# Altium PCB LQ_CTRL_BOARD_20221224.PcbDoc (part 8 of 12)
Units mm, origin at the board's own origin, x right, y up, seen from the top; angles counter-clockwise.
Board outline 260 x 142 mm, 6 copper layers (Top Layer, Mid-Layer 1, Mid-Layer 2, Mid-Layer 3, Mid-Layer 4, Bottom Layer); 1105 components, 1039 nets, 3898 pads, 1277 vias.
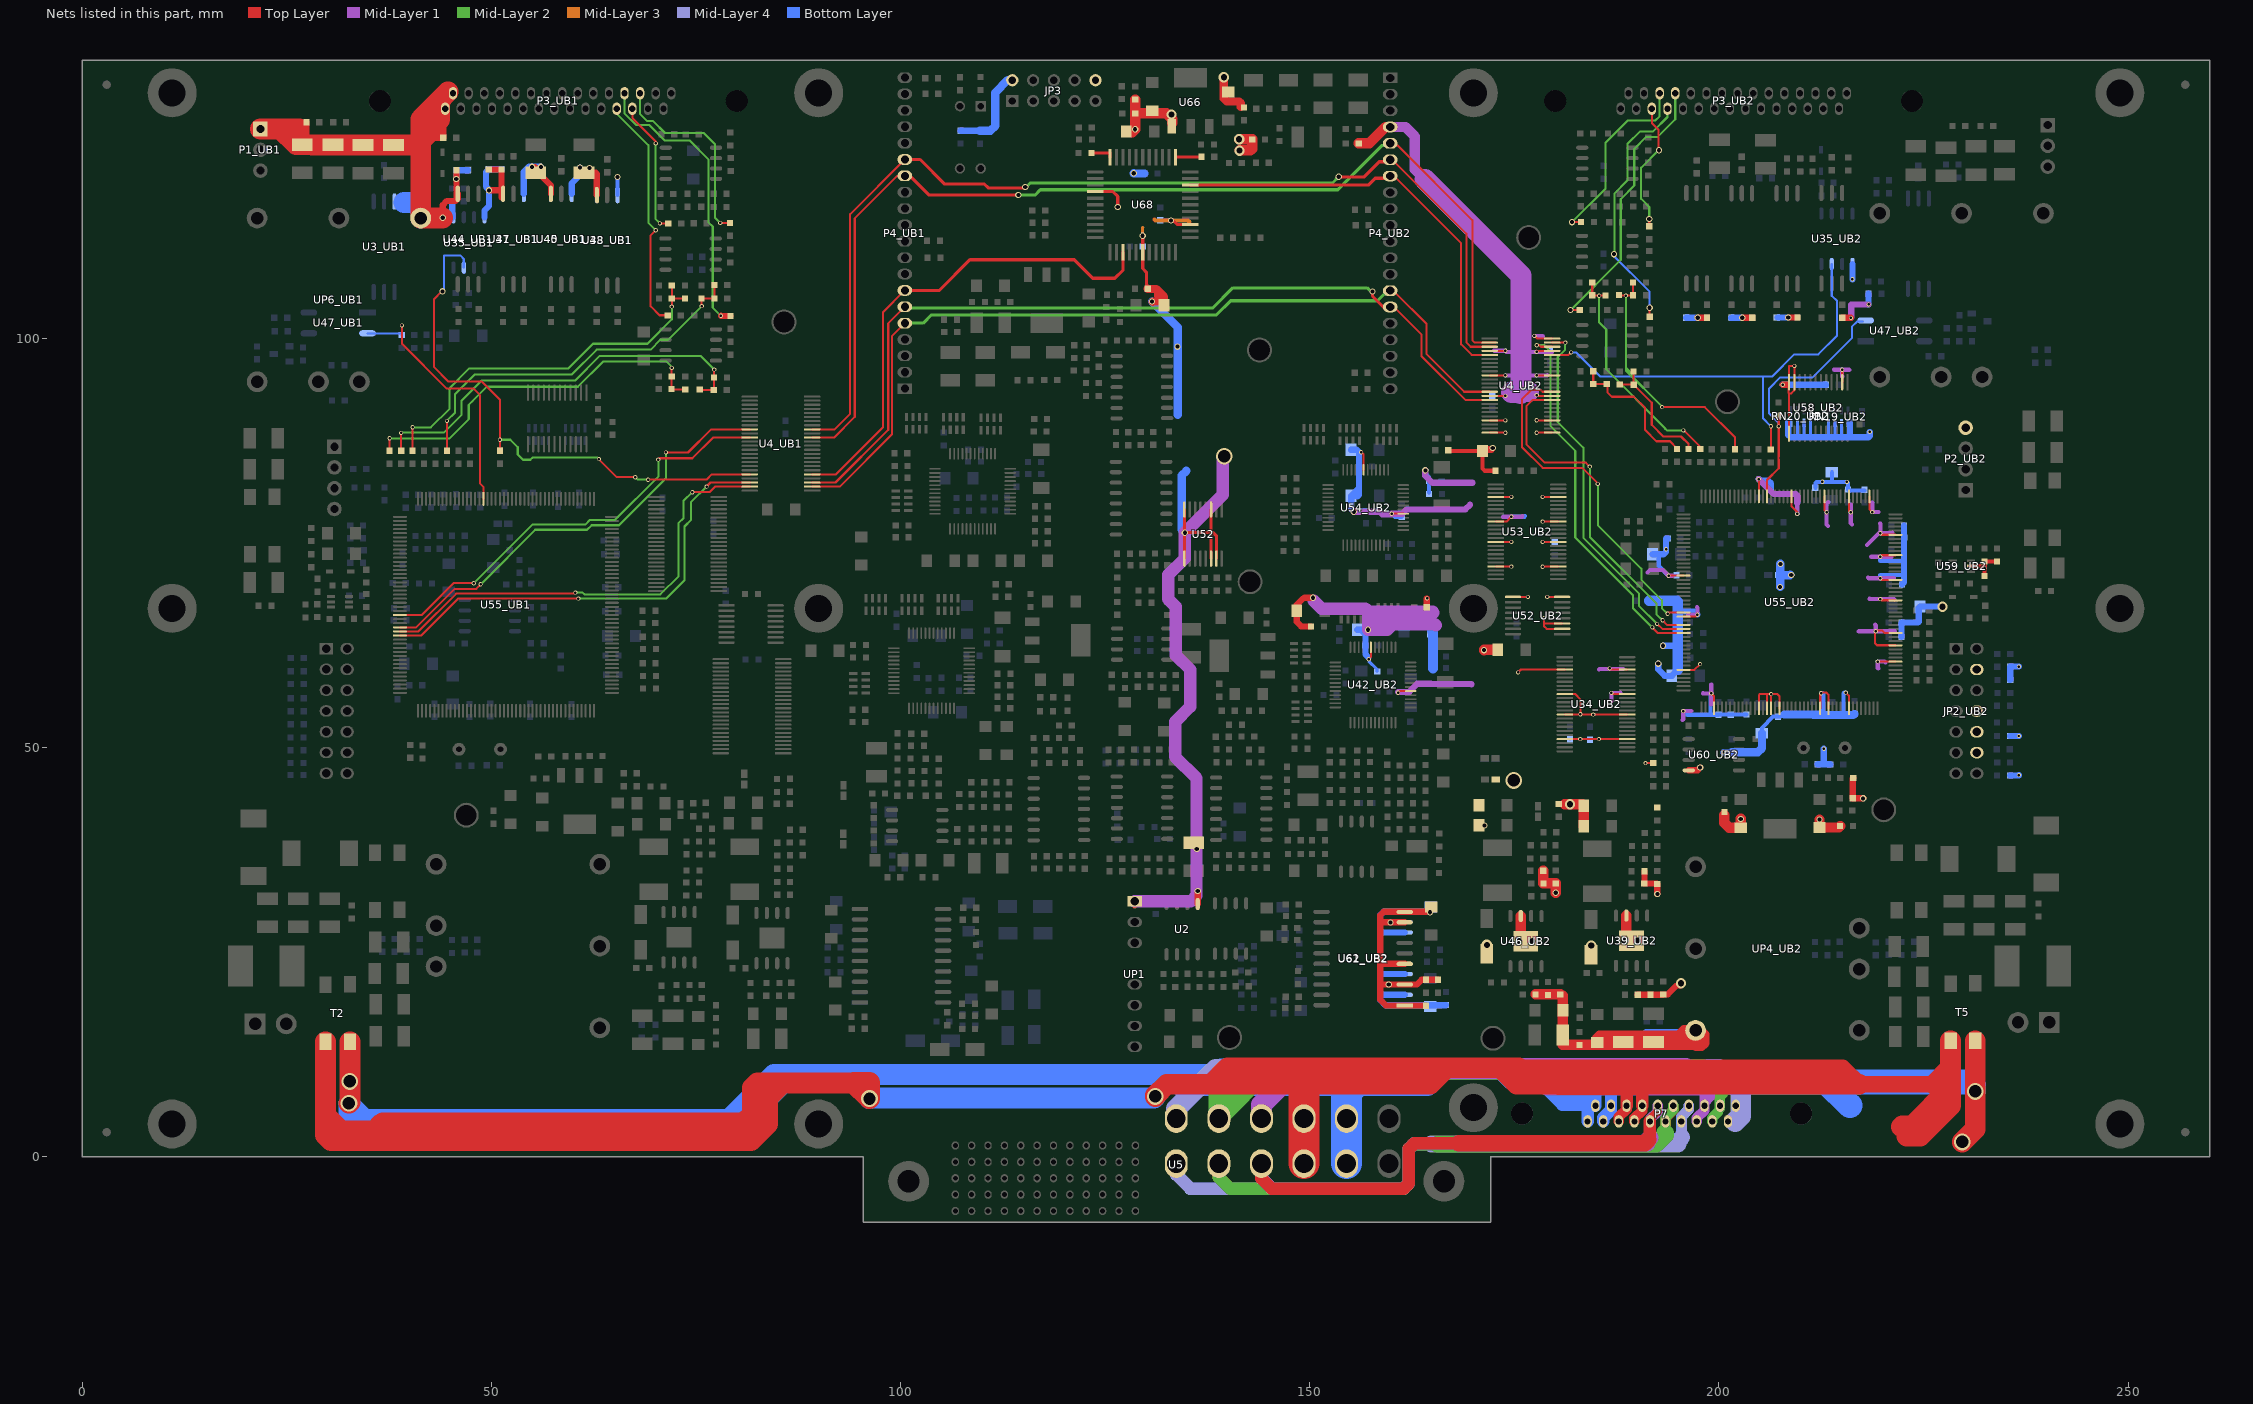
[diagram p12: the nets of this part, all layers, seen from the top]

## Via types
v1: diameter 0.508, hole 0.305, Top Layer to Bottom Layer, 845 vias
v2: diameter 0.762, hole 0.508, Top Layer to Bottom Layer, 317 vias
v3: diameter 1.27, hole 0.762, Top Layer to Bottom Layer, 77 vias
v4: diameter 2.032, hole 1.524, Top Layer to Bottom Layer, 15 vias
v5: diameter 2.032, hole 1.27, Top Layer to Bottom Layer, 11 vias
v6: diameter 1.27, hole 0.711, Top Layer to Bottom Layer, 8 vias
v7: diameter 2.54, hole 1.778, Top Layer to Bottom Layer, 3 vias
v8: diameter 1.524, hole 1.016, Top Layer to Bottom Layer, 1 vias

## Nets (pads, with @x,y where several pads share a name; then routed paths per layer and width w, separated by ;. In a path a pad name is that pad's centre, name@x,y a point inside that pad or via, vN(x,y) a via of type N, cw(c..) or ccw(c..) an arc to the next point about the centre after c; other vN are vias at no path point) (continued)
GND_UB2: C10_UB2.2 C16_UB2.2 C17_UB2.2 C228_UB2.2 C233_UB2.2 C234_UB2.1 C235_UB2.1 C237_UB2.1 C238_UB2.1 C254_UB2.2 C255_UB2.2 C263_UB2.2 C264_UB2.1 C265_UB2.2 C266_UB2.1 C273_UB2.1 C274_UB2.1 C291_UB2.2 C292_UB2.2 C294_UB2.2 C295_UB2.1 C296_UB2.1 C297_UB2.1 C309_UB2.2 C310_UB2.1 C313_UB2.2 C314_UB2.2 C315_UB2.2 C316_UB2.2 C317_UB2.2 C318_UB2.2 C320_UB2.2 C321_UB2.2 C322_UB2.1 C323_UB2.1 C331_UB2.1 C332_UB2.1 C333_UB2.1 C334_UB2.1 C335_UB2.1 C336_UB2.1 C337_UB2.1 C338_UB2.1 C339_UB2.1 C340_UB2.1 C341_UB2.1 C342_UB2.1 C346_UB2.1 C347_UB2.1 C348_UB2.1 C349_UB2.1 C350_UB2.1 C351_UB2.1 C352_UB2.1 C353_UB2.1 C356_UB2.2 C357_UB2.2 C358_UB2.2 C359_UB2.2 C366_UB2.1 C367_UB2.2 C368_UB2.1 C375_UB2.2 C376_UB2.2 C383_UB2.2 C384_UB2.1 C385_UB2.2 C386_UB2.2 C387_UB2.2 C388_UB2.2 C390_UB2.1 C391_UB2.1 C401_UB2.2 C402_UB2.2 C403_UB2.2 C404_UB2.2 C405_UB2.1 C406_UB2.2 C407_UB2.2 C408_UB2.1 C409_UB2.2 C413_UB2.2 C414_UB2.2 C415_UB2.2 C416_UB2.2 C417_UB2.2 C418_UB2.2 C419_UB2.2 D20_UB2.1 D22_UB2.1 JP2_UB2.4 JP2_UB2.8 JP2_UB2.10 JP2_UB2.12 P2_UB2.4 P4_UB2.4 R2.1 R27_UB2.1 R210_UB2.1 R226_UB2.1 R227_UB2.1 R231_UB2.2 R234_UB2.2 R240_UB2.1 R241_UB2.1 R242_UB2.1 R243_UB2.2 R245_UB2.1 R247_UB2.1 R253_UB2.1 R254_UB2.1 R255_UB2.1 R262_UB2.2 R273_UB2.1 R274_UB2.2 R276_UB2.1 R289_UB2.1 R294_UB2.1 R296_UB2.2 R299_UB2.1 R302_UB2.1 R310_UB2.1 R359_UB2.2 R364_UB2.2 RN19_UB2.2 RN19_UB2.4 RN19_UB2.6 RN19_UB2.8 RN20_UB2.2 RN20_UB2.4 RN20_UB2.6 RN20_UB2.8 U4_UB2.4 U4_UB2.10 U4_UB2.15 U4_UB2.21 U4_UB2.24 U4_UB2.25 U4_UB2.28 U4_UB2.34 U4_UB2.39 U4_UB2.45 U4_UB2.48 U34_UB2.4 U34_UB2.10 U34_UB2.15 U34_UB2.21 U34_UB2.28 U34_UB2.34 U34_UB2.39 U34_UB2.45 U35_UB2.5 U39_UB2.7 U39_UB2.9 U42_UB2.5 U42_UB2.19 U46_UB2.7 U46_UB2.9 U52_UB2.2 U52_UB2.3 U52_UB2.8 U52_UB2.9 U53_UB2.4 U53_UB2.10 U53_UB2.15 U53_UB2.21 U53_UB2.28 U53_UB2.34 U53_UB2.39 U53_UB2.45 U54_UB2.5 U54_UB2.19 U55_UB2.3 U55_UB2.8 U55_UB2.14 U55_UB2.22 U55_UB2.30 U55_UB2.60 U55_UB2.70 U55_UB2.83 U55_UB2.92 U55_UB2.103 U55_UB2.105 U55_UB2.106 U55_UB2.108 U55_UB2.118 U55_UB2.120 U55_UB2.125 U55_UB2.140 U55_UB2.144 U55_UB2.147 U55_UB2.155 U55_UB2.160 U55_UB2.166 U55_UB2.171 U58_UB2.2 U58_UB2.11 U58_UB2.12 U58_UB2.13 U59_UB2.2 U60_UB2.4 U61_UB2.1 U61_UB2.3 U61_UB2.7 U61_UB2.9 U61_UB2.10 U62_UB2.1 U62_UB2.3 U62_UB2.5 U62_UB2.9 U62_UB2.10 UP4_UB2.5 | length 718.6
  Top Layer w0.254: v1@156.286,86.182 156.286,86.106 156.592,85.8 U54_UB2.19@156.592,83.923 ; v1(157.226,60.782) 157.484,61.04 U42_UB2.19@157.484,62.25 ; v1(160.02,78.573) U54_UB2.5@161.442,78.573 ; v1@160.807,56.691 161.016,56.9 U42_UB2.5@162.334,56.9 ; U4_UB2.24@172.009,88.474 173.908,88.474 v1(173.914,88.468) ; U4_UB2.21@172.009,89.974 v1(173.914,89.974) ; U4_UB2.15@172.009,92.974 v1(173.914,92.974) ; U4_UB2.10@172.009,95.474 173.91,95.474 v1(173.914,95.479) ; U4_UB2.4@172.009,98.474 v1(173.914,98.474) ; U53_UB2.21@172.745,72.118 174.646,72.118 v1(174.65,72.113) ; U53_UB2.15@172.745,75.118 174.635,75.118 v1(174.65,75.133) ; U53_UB2.10@172.745,77.618 174.062,77.618 v1(174.65,78.206) ; U53_UB2.4@172.745,80.618 174.646,80.618 v1(174.65,80.613) ; U52_UB2.9@174.848,68.406 176.654,68.406 v1(176.657,68.402) ; v1(175.463,59.182) 175.817,59.536 U34_UB2.4@181.178,59.536 ; v1(177.47,100.305) 177.8,99.974 U4_UB2.48@179.629,99.974 ; v1(177.724,88.468) 177.73,88.474 U4_UB2.25@179.629,88.474 ; v1(177.724,89.992) 177.742,89.974 U4_UB2.28@179.629,89.974 ; v1(177.724,95.479) 177.728,95.474 U4_UB2.39@179.629,95.474 ; v1@177.724,98.501 177.751,98.474 U4_UB2.45@179.629,98.474 ; v1@177.861,92.974 U4_UB2.34@179.629,92.974 ; v1(178.46,72.085) 178.493,72.118 U53_UB2.28@180.365,72.118 ; v1(178.46,75.133) 178.475,75.118 U53_UB2.34@180.365,75.118 ; v1(178.46,77.613) 178.465,77.618 U53_UB2.39@180.365,77.618 ; v1(178.46,80.62) 178.462,80.618 U53_UB2.45@180.365,80.618 ; v1(178.638,65.811) 178.638,65.202 ; v1(179.019,68.402) 179.023,68.406 U52_UB2.8@180.848,68.406 ; U52_UB2.2@180.848,64.506 178.953,64.506 178.638,64.821 178.638,65.202 ; U52_UB2.3@180.848,65.156 178.684,65.156 178.638,65.202 ; U34_UB2.21@181.178,51.036 v1(183.058,51.036) U34_UB2.28@188.798,51.036 ; U34_UB2.15@181.178,54.036 v1@182.967,54.036 ; U34_UB2.10@181.178,56.536 182.427,56.536 183.083,55.88 183.083,54.153 v1@182.967,54.036 ; v1@186.639,59.536 U34_UB2.45@188.798,59.536 ; v1(186.868,56.667) 186.999,56.536 U34_UB2.39@188.798,56.536 ; U34_UB2.34@188.798,54.036 v1@182.967,54.036 ; v1(191.033,48.108) R364_UB2.2@191.973,48.108 ; v1@193.751,70.996 U55_UB2.60@195.685,70.996 ; U55_UB2.83@195.685,59.496 197.011,59.496 v1(197.714,60.198) ; U55_UB2.70@195.685,65.996 197.161,65.996 v1(197.383,66.218) ; v1(199.06,56.617) 199.385,56.291 U55_UB2.92@199.385,54.796 ; v1(204.876,82.804) 204.885,82.795 U55_UB2.30@204.885,80.696 ; U55_UB2.103@204.885,54.796 204.885,56.397 205.029,56.54 205.842,56.54 ; U55_UB2.105@205.885,54.796 205.885,56.497 205.842,56.54 ; U55_UB2.106@206.385,54.796 v1@206.385,56.54 ; U55_UB2.108@207.385,54.796 207.385,56.292 207.137,56.54 v1@206.385,56.54 ; 208.304,94.336 208.509,94.131 208.509,93.37 208.585,93.294 208.585,93.269 ; U58_UB2.13@208.569,88.34 208.569,93.253 208.585,93.269 ; U58_UB2.12@208.569,94.64 208.569,96.581 208.61,96.622 v1(209.219,96.622) U58_UB2.11@209.219,94.64 209.219,93.637 208.851,93.269 208.585,93.269 ; U55_UB2.22@208.885,80.696 208.885,79.455 v1@209.6,78.74 ; U55_UB2.118@212.385,54.796 212.385,56.556 212.547,56.718 213.127,56.718 213.385,56.46 U55_UB2.120@213.385,54.796 ; U55_UB2.14@212.885,80.696 212.885,79.012 v1(213.157,78.74) ; v1@215.036,96.266 215.069,96.233 U58_UB2.2@215.069,94.64 ; v1(215.494,56.718) 215.885,56.327 U55_UB2.125@215.885,54.796 ; U55_UB2.8@215.885,80.696 215.885,78.958 v1(216.103,78.74) ; U55_UB2.3@218.385,80.696 218.385,79.125 v1(218.745,78.765) ; v1(219.405,60.496) U55_UB2.140@221.585,60.496 ; v1(219.71,68.148) 219.862,67.996 U55_UB2.155@221.585,67.996 ; v1(219.71,73.304) 219.901,73.496 U55_UB2.166@221.585,73.496 ; v1(219.735,70.688) 219.928,70.496 U55_UB2.160@221.585,70.496 ; v1(219.735,76.191) 219.931,75.996 U55_UB2.171@221.585,75.996 ; U55_UB2.144@221.585,62.496 219.317,62.496 219.075,62.738 219.075,64.262 219.1,64.287 219.964,64.287 220.256,63.996 U55_UB2.147@221.585,63.996 ; 205.842,56.54 v1@206.385,56.54
  Top Layer w0.508: R310_UB2.1@166.918,86.336 167.021,86.233 C309_UB2.2@171.12,86.233 ; C318_UB2.2@172.695,83.82 171.399,83.82 171.12,84.099 C309_UB2.2@171.12,86.233 ; U59_UB2.2@230.804,72.176 232.461,72.176 ; C407_UB2.2@232.461,70.968 v1(232.461,71.907) 232.461,72.176 ; 232.486,72.187 232.476,72.176 232.461,72.176 ; C409_UB2.2@233.979,72.746 R359_UB2.2@232.455,72.746 232.461,72.74 232.461,72.176 ; C309_UB2.2@171.12,86.233 C309_UB2.2@171.247,86.233 ; C309_UB2.2@171.247,86.233 171.628,86.614 172.339,86.614 172.415,86.538 172.415,86.411 172.237,86.233 C309_UB2.2@171.247,86.233
  Top Layer w0.762: 149.2,68.224 148.412,67.437 C265_UB2.2@148.412,66.711 148.412,65.359 148.976,64.795 C266_UB2.1@150.165,64.795 ; 149.352,68.301 v2(150.419,68.301) ; U62_UB2.5@161.615,23.571 158.674,23.571 158.623,23.52 ; U62_UB2.9@161.615,28.651 158.725,28.651 158.623,28.55 ; C414_UB2.2@164.2,18.44 164.149,18.491 U62_UB2.1@161.615,18.491 159.309,18.491 158.623,19.177 158.623,21.006 ; R255_UB2.1@164.313,67.132 164.313,68.199 v1(164.338,68.224) ; C417_UB2.2@164.835,30.505 164.25,29.921 U62_UB2.10@161.615,29.921 159.029,29.921 158.623,29.515 158.623,28.55 ; C419_UB2.2@165.673,21.615 C418_UB2.2@164.207,21.615 163.678,21.615 163.093,21.031 U62_UB2.3@161.615,21.031 v2(159.664,21.031) 158.648,21.031 158.623,21.006 ; C264_UB2.1@190.094,19.787 R243_UB2.2@191.643,19.787 193.142,19.787 C273_UB2.1@193.192,19.837 193.777,19.837 194.869,20.93 v3@195.301,20.93 ; R245_UB2.1@190.906,34.874 190.906,33.396 C274_UB2.1@190.886,33.376 192.43,33.376 R242_UB2.1@192.481,33.325 v2(192.481,32.106) ; U60_UB2.4@196.312,47.219 197.409,47.219 197.409,47.269 v2(197.714,47.574) ; v2@197.383,102.514 R227_UB2.1@198.552,102.514 ; v2@202.87,102.514 R254_UB2.1@204.069,102.514 ; v1(207.797,94.336) 208.304,94.336 208.33,94.361 ; v2(208.483,102.54) R241_UB2.1@209.601,102.54 ; R253_UB2.1@215.067,102.514 216.103,102.514 v1(216.129,102.489) ; R294_UB2.1@216.408,46.279 216.357,46.228 C321_UB2.2@216.357,43.815 217.602,43.815 v2(217.627,43.79) ; 158.623,21.006 158.623,23.52 ; 158.623,23.52 158.623,28.55
  Top Layer w1.27: R2.1@155.981,123.825 157.272,123.825 159.273,125.826 P4_UB2.4@159.842,125.826 ; v2(171.298,61.9) 171.298,61.951 C383_UB2.2@172.974,61.951 ; U46_UB2.7@175.793,29.413 175.793,26.949 U46_UB2.9@176.403,26.34 ; C295_UB2.1@177.597,19.837 C296_UB2.1@180.619,19.837 ; R276_UB2.1@178.537,34.95 178.562,34.925 C297_UB2.1@178.562,33.401 R273_UB2.1@180.066,33.401 180.066,32.263 v2(180.061,32.258) ; C17_UB2.2@180.899,13.665 R210_UB2.1@182.982,13.665 195.379,13.665 ; C17_UB2.2@180.924,14.732 C296_UB2.1@180.924,19.685 ; v3@181.178,43.078 183.312,43.078 C255_UB2.2@183.49,42.901 C254_UB2.2@183.49,40.361 ; C263_UB2.2@185.115,13.945 185.115,14.478 185.445,14.808 194.64,14.808 ; U39_UB2.7@188.697,29.464 188.697,27 U39_UB2.9@189.306,26.391 ; 200.66,41.707 200.66,40.792 201.244,40.208 C313_UB2.2@202.692,40.208 202.692,41.25 v2(202.667,41.275) ; v2(212.293,41.199) C314_UB2.2@212.293,40.234 214.63,40.234 R289_UB2.1@214.808,40.411 ; 195.379,13.665 197.125,13.665 ; 195.379,13.665 UP4_UB2.5@196.522,14.808 ; UP4_UB2.5@196.522,14.808 195.123,14.808 195.751,15.436 UP4_UB2.5@197.15,15.436 ; UP4_UB2.5@196.522,14.808 UP4_UB2.5@197.125,15.411 ; 197.125,13.665 197.252,13.538 197.866,13.538 198.145,13.818 198.145,13.894 198.196,13.945 198.196,14.91 197.67,15.436 UP4_UB2.5@197.15,15.436 ; 197.125,13.665 UP4_UB2.5@197.125,15.411 ; UP4_UB2.5@197.125,15.411 UP4_UB2.5@197.15,15.436
  Mid-Layer 1 w0.508: 172.542,98.501 172.569,98.474 v1(173.914,98.474) 174.039,98.349 175.819,98.349 176.733,98.349 ; 173.634,78.181 173.659,78.206 v1(174.65,78.206) 175.945,78.206 175.997,78.257 ; v1(173.914,95.479) 175.819,95.479 176.2,95.479 ; 176.124,95.402 176.2,95.479 ; 176.632,98.247 176.733,98.349 ; v1(177.47,100.305) 178.435,100.305 178.486,100.254 ; 179.019,95.504 178.994,95.479 v1(177.724,95.479) 176.2,95.479 ; 179.603,98.298 179.553,98.349 v1(177.724,98.349) 176.733,98.349 ; 185.344,59.549 185.408,59.614 188.316,59.614 ; 186.868,55.677 v1(186.868,56.667) 187.936,56.667 187.96,56.691 ; 191.287,71.374 191.592,71.679 193.167,71.679 v1(193.853,70.993) 194.371,70.993 ; 195.555,53.365 195.649,53.459 v1(195.649,54.458) 196.61,54.458 196.621,54.469 ; 196.266,66.218 v1(197.383,66.218) 197.383,67.081 197.333,67.132 ; 198.069,56.642 198.095,56.617 v1(199.06,56.617) ; 199.06,55.245 v1(199.06,56.617) ; 199.085,57.709 199.06,57.683 v1(199.06,56.617) ; v1(209.575,78.537) 209.575,79.883 209.728,80.035 ; 213.335,77.089 213.157,77.267 v1(213.157,78.74) 213.157,79.807 213.36,80.01 ; 214.071,96.19 214.097,96.164 v1(215.062,96.164) ; 215.087,95.326 215.062,95.352 v1(215.062,96.164) ; 215.925,96.139 215.9,96.164 v1(215.062,96.164) ; 216.154,79.705 216.103,79.654 v1(216.103,78.74) 216.103,77.419 216.281,77.241 ; 217.094,64.186 217.119,64.211 v1(219.177,64.211) ; 218.11,74.752 219.549,76.191 v1(219.735,76.191) ; 218.211,70.79 218.313,70.688 v1(219.735,70.688) 221.336,70.688 221.361,70.714 221.361,70.688 ; 218.415,68.174 218.44,68.148 v1(219.71,68.148) 221.386,68.148 221.437,68.097 ; 218.618,73.304 v1(219.71,73.304) 221.056,73.304 221.082,73.279 ; 218.719,79.934 218.745,79.908 v1(218.745,78.765) 219.481,78.765 219.507,78.791 ; 219.1,64.999 219.177,64.922 v1(219.177,64.211) ; 219.481,59.639 219.405,59.715 v1(219.405,60.496) 220.276,60.496 220.37,60.401 ; 219.685,77.394 219.735,77.343 v1(219.735,76.191) ; 221.234,76.251 221.174,76.191 v1(219.735,76.191) ; 221.539,64.186 221.513,64.211 v1(219.177,64.211)
  Mid-Layer 1 w0.762: v2(155.396,78.816) 158.572,78.816 158.877,78.511 159.958,78.511 v1(160.02,78.573) 161.327,78.573 161.849,79.096 164.744,79.096 ; v1@160.807,56.794 162.154,56.794 163.144,57.785 164.414,57.785 ; v2(164.135,83.871) 164.135,83.21 164.998,82.347 169.901,82.347 ; 164.744,79.087 164.744,79.096 ; 164.795,57.785 164.414,57.785 ; 169.596,79.68 169.012,79.096 164.744,79.096 ; 169.774,57.734 169.774,57.76 164.44,57.76 164.414,57.785 ; v1(204.876,82.804) 206.705,80.975 209.398,80.975 209.575,80.797 209.575,79.883 ; v1(216.129,102.489) 216.179,102.54 216.179,104.089 216.23,104.14 v1(218.288,104.14)
  Mid-Layer 1 w1.27: P4_UB2.4@159.842,125.826 161.677,125.826 162.839,124.663 162.839,120.65 164.084,119.405
  Mid-Layer 1 w1.524: v2@150.508,67.932 151.46,66.98 156.794,66.98 157.175,66.599 ; 165.125,66.497 165.024,66.599 157.175,66.599 ; 165.405,64.922 165.278,65.049 160.096,65.049 ; v2@157.175,64.44 157.785,65.049 160.096,65.049 ; v2@157.175,64.44 v2(157.124,64.389) 159.436,64.389 160.096,65.049 ; v2@157.175,64.44 157.175,66.599
  Mid-Layer 1 w2.54: 164.084,119.405 175.819,107.671 175.819,98.349 175.819,95.479 175.819,93.497 ; 176.733,93.497 175.819,93.497 ; 175.819,93.497 174.752,93.497 174.65,93.396 175.616,93.396 175.743,93.269 175.819,93.345 175.819,93.497
  Bottom Layer w0.254: C387_UB2.2@172.314,92.964 173.903,92.964 v1(173.914,92.974) ; v1(177.724,98.349) 179.172,98.349 C316_UB2.2@179.375,98.552 ; v1(178.46,75.133) 179.908,75.133 C388_UB2.2@179.934,75.108 ; C386_UB2.2@181.813,51.003 181.846,51.036 v1(183.058,51.036) ; v1(193.853,70.993) 193.904,71.044 C334_UB2.1@194.818,71.044
  Bottom Layer w0.381: v1(157.226,60.782) 157.226,60.554 158.242,59.538 C237_UB2.1@158.242,59.284 ; 209.601,87.909 209.607,87.916 RN20_UB2.4@209.607,89.687 ; 210.388,87.909 210.407,87.928 RN20_UB2.6@210.407,89.687 ; 211.125,87.909 211.207,87.992 RN20_UB2.8@211.207,89.687 ; 213.36,87.909 213.376,87.926 RN19_UB2.2@213.376,89.662 ; 214.147,87.909 214.176,87.938 RN19_UB2.4@214.176,89.662 ; RN19_UB2.6@214.976,89.662 214.976,87.944 215.011,87.909 ; RN19_UB2.8@215.777,89.531 RN19_UB2.8@215.777,89.662
  Bottom Layer w0.508: v1(160.02,78.573) 160.432,78.162 C405_UB2.1@161.239,78.162 ; v2(164.135,83.871) 164.109,83.871 164.186,83.795 164.186,83.424 164.567,83.043 C384_UB2.1@164.567,82.575 164.567,81.178 C390_UB2.1@164.592,81.153 ; v1(174.65,78.206) 176.25,78.206 176.327,78.283 ; 192.659,73.613 192.659,72.187 v1(193.853,70.993) ; v1@195.809,54.331 196.139,54 199.085,54 ; v1(199.06,56.617) 198.984,56.54 198.984,54.102 199.085,54 ; C337_UB2.1@203.378,54.051 200,54.051 C351_UB2.1@199.949,54 199.085,54 ; C358_UB2.2@205.257,51.74 205.257,52.4 206.629,53.772 C338_UB2.1@207.239,53.772 207.569,53.772 207.899,54.102 211.404,54.102 211.48,54.026 C339_UB2.1@211.531,53.975 ; C332_UB2.1@211.785,81.737 211.785,82.321 211.912,82.448 213.817,82.448 ; v1(212.496,56.642) 212.674,56.642 212.7,56.667 212.75,56.617 212.75,53.975 ; C356_UB2.2@213.817,83.642 213.817,82.448 ; 215.163,53.975 215.214,54.026 215.214,56.617 215.316,56.718 v1(215.494,56.718) ; C331_UB2.1@217.78,81.407 215.904,81.407 C406_UB2.2@215.777,81.534 215.777,82.343 215.671,82.448 213.817,82.448 ; v1(219.71,73.304) 219.71,72.822 219.735,72.796 222.631,72.796 ; v1(219.735,70.688) 219.735,71.044 219.71,71.069 222.606,71.069 222.631,71.044
  Bottom Layer w0.762: C385_UB2.2@155.042,86.385 155.727,86.385 156.032,86.081 C391_UB2.1@156.032,84.353 156.032,81.737 ; C315_UB2.2@155.804,64.389 C315_UB2.2@156.261,64.389 ; C238_UB2.1@156.921,78.816 v2(155.396,78.816) 155.067,79.146 C228_UB2.2@155.067,80.772 ; v2(157.124,64.389) C315_UB2.2@156.261,64.389 ; 157.175,61.036 156.82,61.392 C317_UB2.2@156.82,62.459 156.82,63.83 C315_UB2.2@156.261,64.389 ; U61_UB2.9@161.609,19.787 158.623,19.787 158.598,19.761 ; U61_UB2.7@161.609,22.327 158.598,22.327 ; U61_UB2.3@161.609,27.407 158.648,27.407 158.598,27.356 ; C413_UB2.2@164.809,30.505 164.25,29.947 U61_UB2.1@161.609,29.947 159.029,29.947 158.598,29.515 158.598,27.356 ; C416_UB2.2@166.663,18.542 166.638,18.517 U61_UB2.10@161.609,18.517 159.258,18.517 158.598,19.177 158.598,19.761 ; C359_UB2.2@191.897,73.613 192.659,73.613 193.247,73.613 193.548,73.914 v1(193.548,74.219) ; v2(192.583,60.249) 192.583,59.563 193.396,58.75 C402_UB2.2@194.234,58.75 194.97,59.487 195.072,59.588 195.072,62.433 194.97,62.433 C401_UB2.2@194.869,62.433 ; v2(193.167,62.433) C401_UB2.2@194.869,62.433 ; v1@193.548,74.32 193.548,75.54 C336_UB2.1@193.751,75.54 ; R247_UB2.1@196.012,102.514 v2(197.409,102.514) ; v1@197.383,66.269 197.028,66.624 195.428,66.624 194.97,66.167 194.894,66.091 C352_UB2.1@194.894,65.303 C353_UB2.1@194.894,63.881 194.894,62.459 C401_UB2.2@194.869,62.433 ; v1(200.533,49.428) C408_UB2.1@201.574,49.428 ; R240_UB2.1@201.504,102.489 R240_UB2.1@201.529,102.514 v2(202.855,102.514) ; v1(204.876,82.804) 205.08,82.601 206.045,82.601 206.375,82.271 C335_UB2.1@206.375,81.661 ; R226_UB2.1@207.188,102.54 v2(208.483,102.54) ; v1(207.797,94.336) C368_UB2.1@213.081,94.336 ; 208.483,89.814 208.483,88.189 208.763,87.909 209.601,87.909 210.388,87.909 211.125,87.909 213.36,87.909 214.147,87.909 215.011,87.909 216.002,87.909 ; C403_UB2.2@212.065,47.955 212.827,47.955 ; v1(212.827,49.86) 212.827,47.955 ; C404_UB2.2@213.614,47.93 213.589,47.955 212.827,47.955 ; 216.027,89.764 216.027,87.935 216.002,87.909 ; v1(216.318,107.213) 216.332,107.213 U35_UB2.5@216.332,109.093 ; v1(218.288,104.14) R27_UB2.1@218.288,105.435 ; v1(218.44,88.57) 218.44,88.062 218.288,87.909 216.002,87.909 ; C341_UB2.1@222.326,63.5 C333_UB2.1@222.326,65.278 224.333,65.278 224.434,65.38 224.434,67.081 C357_UB2.2@224.587,67.234 227.287,67.234 v3(227.33,67.191) ; C349_UB2.1@222.377,69.926 222.631,70.18 222.631,71.044 222.631,72.796 C342_UB2.1@222.631,74.193 C346_UB2.1@222.631,77.14 ; C375_UB2.2@235.56,46.584 236.652,46.584 v1(236.652,46.634) ; C376_UB2.2@235.56,51.41 v1(236.652,51.41) ; C366_UB2.1@235.616,58.268 235.616,59.842 R302_UB2.1@235.59,59.868 235.616,59.893 v1(236.652,59.893) ; C228_UB2.2@155.067,80.772 156.032,81.737 ; C228_UB2.2@155.067,80.772 155.778,80.772 155.854,80.696 156.032,80.874 156.032,81.737 ; 158.598,19.761 158.598,22.327 ; 158.598,22.327 158.598,27.356
  Bottom Layer w1.016: C408_UB2.1@201.574,49.428 204.775,49.428 205.257,49.911 C358_UB2.2@205.257,51.74 ; v2@207.493,69.621 R296_UB2.2@207.493,71.069 ; v2@207.518,72.466 207.493,72.441 R296_UB2.2@207.493,71.069 ; 207.975,54.026 211.48,54.026 212.09,54.026 212.141,53.975 ; v2@208.712,71.095 208.686,71.069 R296_UB2.2@207.493,71.069 ; C339_UB2.1@211.531,53.975 212.141,53.975 ; C340_UB2.1@216.56,54.102 216.433,53.975 215.163,53.975 212.75,53.975 212.141,53.975
  Bottom Layer w1.27: C367_UB2.2@164.973,64.237 165.075,64.135 C310_UB2.1@165.075,61.138 C322_UB2.1@165.075,59.702 ; C235_UB2.1@191.186,14.961 196.674,14.961 UP4_UB2.5@197.15,15.436 ; R299_UB2.1@191.491,67.945 194.869,67.945 194.97,67.843 194.97,66.167 194.97,62.433 194.97,59.487
  other v1: 185.344,51.038 184.658,54.035 183.083,54.077 206.377,56.54 160.807,56.693 186.639,59.663 215.646,82.448 212.649,82.474 156.286,86.08 177.749,93.066
  other v2: 159.868,28.626 164.694,29.87 171.374,40.488 207.467,69.621 208.839,71.095 207.518,72.441 172.364,86.589
  other v3: 195.375,21.209 184.404,25.806 171.653,25.883 177.241,26.365 175.514,26.391 188.392,26.416 190.043,26.416 181.813,43.078
  other v4: 174.93,45.974
GNDMS: C3.2 C4.2 C436.2 C437.2 C438.2 C439.2 C449.1 C450.1 C451.1 C452.1 C453.1 C454.1 JP3.2 JP3.10 R32.2 R34.2 R389.2 R395.1 U2.5 U52.3 U52.8 U52.9 U52.14 U52.15 U66.1 U68.4 U68.17 U68.25 UP1.1 | length 174.4
  Top Layer w0.381: U68.4@123.8,117.92 125.971,117.92 126.543,117.348 v2(126.543,116.053) ; v2(129.591,112.527) 129.6,112.519 U68.17@129.6,110.52 129.6,108.525 130.048,108.077 130.048,106.248 C450.1@130.226,106.07 ; v2(133.045,114.402) 133.325,114.402 133.806,113.92 U68.25@135.4,113.92 ; U52.9@134.693,73.087 v2@134.693,76.276 ; U52.8@134.693,79.087 v2@134.693,76.276 ; U52.14@137.943,73.087 137.943,76.276 ; U52.3@137.943,79.087 137.943,76.526 ; U52.15@138.593,73.087 138.593,75.884 138.201,76.276 137.943,76.276 ; v2@134.693,76.276 137.693,76.276 ; 137.693,76.276 137.943,76.526 ; 137.693,76.276 137.943,76.276 ; 137.943,76.276 137.943,76.526
  Top Layer w0.762: U2.5@136.322,30.886 v2@136.322,32.41
  Top Layer w1.016: C450.1@130.226,106.07 130.277,106.02 131.267,106.02 131.496,105.791 ; v2@130.835,104.47 130.861,104.496 C449.1@132.207,104.496 ; C449.1@132.207,104.064 C449.1@132.207,104.496 ; v3@139.522,131.877 139.502,131.857 139.502,129.306 139.878,128.93 141.376,128.93 141.58,128.727 C438.2@141.58,128.27 ; 131.496,105.791 131.496,105.207 C449.1@132.207,104.496 ; 131.496,105.791 132.207,105.08 C449.1@132.207,104.496
  Top Layer w1.27: 128.326,125.197 v2(128.676,125.547) R395.1@128.676,127.457 C439.2@128.676,129.184 ; 129.159,127.483 132.486,127.483 133.198,126.771 U66.1@133.198,126.34 ; v3@141.376,124.308 R389.2@142.977,124.308 142.977,123.165 142.773,122.961 v3@141.453,122.961
  Mid-Layer 1 w1.524: UP1.1@128.626,31.217 135.484,31.217 136.169,31.902 136.169,46.253 133.553,48.87 133.553,53.137 135.407,54.991 135.407,59.51 133.629,61.288 133.629,67.234 132.715,68.148 132.715,71.095 134.747,73.127 v2(134.747,76.251) 139.37,80.874 v4@139.37,85.547
  Mid-Layer 3 w0.381: 129.616,110.998 129.591,111.023 v2(129.591,112.527) 129.591,113.538 129.616,113.563
  Mid-Layer 3 w0.508: 131.039,114.529 131.166,114.402 v2(133.045,114.402) 135.128,114.402 135.28,114.249
  Mid-Layer 3 w0.762: UP1.1@128.626,30.734 UP1.1@128.626,31.217
  Bottom Layer w0.381: C454.1@129.591,111.227 v2(129.591,112.527) ; C453.1@131.75,114.427 133.02,114.427 v2(133.045,114.402)
  Bottom Layer w0.762: R34.2@107.34,125.374 109.677,125.374 R32.2@109.703,125.349 ; UP1.1@128.473,31.064 UP1.1@128.626,31.217 ; UP1.1@129.21,31.267 C4.2@131.166,31.267
  Bottom Layer w1.016: R32.2@109.677,125.374 110.998,125.374 111.582,125.959 111.582,130.023 113.099,131.54 JP3.2@113.665,131.54 ; v2(128.499,120.167) 128.524,120.142 C451.1@129.819,120.142 ; v2(130.734,104.496) 133.883,101.346 v2@133.883,98.984 ; v2(133.858,98.984) v2@133.883,98.984 ; 133.883,90.678 v2@133.883,98.984 ; v2(134.747,76.251) 134.366,76.632 134.366,83.247 134.925,83.805
  other v2: 136.322,32.461 136.195,37.592
  other v3: 141.427,122.936 141.376,124.333 133.121,127.356 139.522,131.902
  other v4: 139.573,85.573
HVA1: P7.1 P7.11 U5.1 | length 101.9
  Mid-Layer 4 w2.54: U5.1@133.7,4.663 133.7,5.862 138.532,10.693 177.749,10.693 ; 202.006,4.318 202.667,4.978 202.667,8.001 201.701,8.966 ; 177.749,10.693 199.974,10.693 201.701,8.966 ; 177.749,10.693 179.476,8.966 201.701,8.966
HVA2: P7.4 P7.14 U5.7 | length 146.1
  Mid-Layer 4 w1.27: 195.478,2.362 195.478,4.953 196.342,5.817 P7.4@196.342,6.223
  Mid-Layer 4 w1.524: U5.7@133.7,-0.837 133.7,-2.179 135.429,-3.908 161.497,-3.908 162.108,-3.297 162.108,0.996 162.662,1.549 164.846,1.549
  Mid-Layer 4 w2.032: 164.846,1.549 195.021,1.549 ; 195.021,1.905 195.478,2.362
  Bottom Layer w1.27: 195.072,1.956 195.389,2.273 P7.14@195.389,4.318 195.389,4.839 196.342,5.791 P7.4@196.342,6.223
  Bottom Layer w1.524: U5.7@133.7,-0.837 133.7,-2.179 135.429,-3.908 161.468,-3.908 162.108,-3.268 162.108,0.945 162.789,1.626 168.453,1.626
  Bottom Layer w2.032: 168.453,1.626 194.742,1.626 195.072,1.956
HVB1: P7.2 P7.12 U5.2 | length 96.2
  Mid-Layer 2 w1.27: P7.12@199.2,4.318 199.2,4.737 199.873,5.41 ; 199.873,8.433 200.025,8.585 200.05,8.611 ; P7.2@200.101,5.944 200.101,8.966
  Mid-Layer 2 w2.54: U5.2@138.9,4.663 U5.2@138.9,4.991 ; 138.913,8.712 138.9,8.7 U5.2@138.9,4.991 ; 200.025,8.153 200.025,8.585 ; 200.05,8.611 199.644,9.017 ; U5.2@138.9,4.991 144.602,10.693 177.673,10.693 ; 177.673,10.693 197.968,10.693 199.644,9.017 ; 177.673,10.693 179.349,9.017 199.644,9.017
HVB2: P7.5 P7.15 U5.8 | length 132
  Mid-Layer 2 w1.27: 193.472,2.642 193.472,2.921 193.472,4.75 194.437,5.715 P7.5@194.437,6.223
  Mid-Layer 2 w1.524: U5.8@138.9,-0.837 138.9,-2.527 140.28,-3.908 161.395,-3.908 162.108,-3.195 162.108,0.996 162.636,1.524 165.583,1.524
  Mid-Layer 2 w2.032: 165.583,1.524 192.354,1.524 193.472,2.642 ; 193.421,2.972 193.472,2.921
  Mid-Layer 3 w1.27: 193.446,2.718 193.484,2.756 P7.15@193.484,4.318 193.484,4.737 194.437,5.69 P7.5@194.437,6.223
  Mid-Layer 3 w1.524: U5.8@138.9,-0.837 138.9,-2.527 140.28,-3.908 161.468,-3.908 162.108,-3.268 162.108,1.021 162.687,1.6 168.021,1.6
  Mid-Layer 3 w2.032: 168.021,1.6 192.329,1.6 193.446,2.718
HVC1: P7.3 P7.13 U5.3 | length 88.3
  Mid-Layer 1 w1.27: P7.13@197.294,4.318 197.294,4.737 198.247,5.69 P7.3@198.247,6.223 P7.3@198.247,6.655 ; 197.968,8.763 198.247,8.484 P7.3@198.247,6.655 ; 198.018,9.398 198.907,8.509 198.907,7.315 P7.3@198.247,6.655
  Mid-Layer 1 w2.54: U5.3@144.1,4.663 144.1,6.356 148.514,10.77 177.013,10.77 ; 177.013,10.77 195.961,10.77 197.968,8.763 179.019,8.763 177.013,10.77
HVC2: P7.6 P7.16 U5.9 | length 118.1
  Top Layer w1.016: P7.16@191.579,4.318 191.579,4.635 192.532,5.588 P7.6@192.532,6.223
  Top Layer w1.524: U5.9@144.1,-0.837 144.1,-2.647 145.36,-3.908 161.442,-3.908 162.108,-3.242 162.108,0.945 162.789,1.626 168.199,1.626 ; 191.389,2.083 191.579,2.273 P7.16@191.579,4.318
  Top Layer w2.032: 168.199,1.626 190.932,1.626 191.389,2.083
  Mid-Layer 1 w1.27: 191.579,2.299 P7.16@191.579,4.318 191.579,4.571 192.532,5.523 P7.6@192.532,6.223
  Mid-Layer 1 w1.524: U5.9@144.1,-0.837 144.1,-2.622 145.386,-3.908 161.417,-3.908 162.108,-3.217 162.108,0.945 162.789,1.626 168.148,1.626
  Mid-Layer 1 w2.032: 168.148,1.626 191.262,1.626 ; 191.262,1.981 191.579,2.299
HVCC: P7.7 P7.8 P7.17 P7.18 T2.4 T5.4 U5.4 U5.10 | length 423.7
  Top Layer w1.27: P7.18@187.769,4.318 187.769,4.864 188.722,5.817 P7.8@188.722,6.223 ; P7.17@189.674,4.318 189.674,4.686 190.627,5.639 P7.7@190.627,6.223
  Top Layer w1.524: 179.807,8.865 180.365,8.306 180.365,8.865 ; 180.442,8.306 182.296,8.306 ; 182.27,8.331 182.296,8.306 ; P7.8@188.722,6.223 188.722,7.772 188.214,8.28 ; P7.7@190.627,6.223 190.627,8.28 188.214,8.28 ; 182.296,8.306 186.385,8.306 ; 186.385,8.306 188.189,8.306 188.214,8.28 ; 186.385,8.306 186.411,8.28 188.214,8.28
  Top Layer w2.032: 175.514,10.871 176.86,10.871 215.113,10.871 217.119,8.865 226.314,8.865
  Top Layer w2.54: T2.4@29.741,14.057 29.741,5.032 ; v4@96.19,7.087 94.259,9.017 ; v4(96.215,7.112) 96.215,9.068 96.19,9.093 94.336,9.093 94.259,9.017 ; v4(131.14,7.366) 131.14,7.468 132.537,8.865 137.973,8.865 ; 175.514,10.871 173.304,10.871 ; 217.119,8.865 180.365,8.865 179.807,8.865 178.867,8.865 175.311,8.865 173.304,10.871 ; 222.301,3.658 222.428,3.785 223.644,3.785 228.318,8.458 ; 222.961,2.515 224.587,2.515 228.318,6.246 228.318,8.458 ; 228.318,11.963 228.318,10.868 ; T5.4@228.318,14.184 228.318,10.868 ; 29.741,5.032 29.741,2.67 30.429,1.981 32.791,1.981 ; 29.741,5.032 31.623,3.15 ; 31.623,3.15 32.791,1.981 ; 31.623,3.15 35.712,3.15 36.728,4.166 80.874,4.166 81.89,5.182 81.89,8.382 82.525,9.017 85.598,9.017 ; 32.791,1.981 81.737,1.981 83.744,3.988 83.744,7.163 85.598,9.017 ; 85.598,9.017 94.259,9.017 ; 137.973,8.865 149.25,8.865 152.917,8.865 ; 137.973,8.865 139.979,10.871 154.924,10.871 ; 152.917,8.865 154.924,10.871 ; 152.917,8.865 160.528,8.865 ; 154.924,10.871 162.535,10.871 ; 160.528,8.865 162.535,10.871 ; 160.528,8.865 164.694,8.865 166.7,10.871 ; 162.535,10.871 166.7,10.871 ; 166.7,10.871 173.304,10.871 ; 228.318,8.458 228.318,10.868 ; 228.318,8.458 227.911,8.865 226.314,8.865 228.318,10.868
  Top Layer w3.81: 149.25,8.865 149.3,8.815 U5.4@149.3,4.663 U5.10@149.3,-0.837
  Bottom Layer w2.54: v4(96.215,7.112) 96.266,7.163 130.988,7.163 v4@131.14,7.315
HVGND: P7.9 P7.10 P7.19 P7.20 T2.2 T5.2 U5.5 U5.11 | length 407.2
  Top Layer w2.54: v4(32.614,6.528) 32.741,6.655 T2.2@32.741,14.057 ; v4(229.743,1.803) 231.318,3.378 v4(231.318,7.976) T5.2@231.318,14.184
  Bottom Layer w1.524: 176.428,10.465 172.949,10.465 174.371,9.042 177.851,9.042 ; 177.749,10.82 176.428,10.82 176.505,10.744 180.873,6.375 ; 180.873,7.239 180.873,6.375 ; P7.20@183.959,4.318 183.959,6.375 ; P7.19@185.864,4.318 185.864,4.75 186.817,5.703 P7.9@186.817,6.223 186.817,8.661 186.487,8.992 185.293,8.992 ; 230.988,8.992 231.775,8.992 231.902,8.865 ; 180.873,6.375 183.959,6.375 ; 181.432,8.001 180.442,8.992 185.293,8.992 ; 181.432,8.001 182.169,7.264 182.423,7.518 183.718,7.518 ; 181.432,8.001 184.429,8.001 184.912,7.518 ; 183.718,7.518 184.912,7.518 ; 183.718,7.518 183.959,7.277 183.959,6.375 ; 183.959,6.375 184.76,6.375 P7.10@184.912,6.223 184.912,7.518 ; 184.912,7.518 184.912,8.611 185.293,8.992
  Bottom Layer w2.032: 134.137,8.636 134.188,8.687
  Bottom Layer w2.54: v4(32.614,6.528) 32.614,3.81 34.061,2.362 81.255,2.362 83.718,4.826 83.718,7.036 ; v4@32.69,6.375 34.519,4.547 79.019,4.547 ; 160.518,10.531 158.674,8.687 ; 180.442,8.992 178.689,10.744 176.505,10.744 166.446,10.744 ; 230.988,8.992 231.318,8.661 v4(231.318,7.976) ; 79.019,4.547 81.229,4.547 82.067,5.385 ; 79.019,4.547 82.067,7.595 ; 82.067,5.385 83.718,7.036 ; 82.067,5.385 82.067,7.595 ; 82.067,7.595 84.531,10.058 93.767,10.058 ; 83.718,7.036 85.801,9.119 92.827,9.119 93.767,10.058 ; 93.767,10.058 132.817,10.058 ; 132.817,10.058 138.557,10.058 ; 132.817,10.058 134.188,8.687 137.185,8.687 ; 137.185,8.687 155.194,8.687 158.674,8.687 ; 137.185,8.687 138.557,10.058 ; 138.557,10.058 139.243,10.744 140.741,10.744 ; 138.557,10.058 140.056,10.058 140.741,10.744 ; 140.741,10.744 166.446,10.744 ; 158.674,8.687 164.389,8.687 166.446,10.744
  Bottom Layer w3.048: 179.273,9.144 213.106,9.144 ; 216.002,6.248 213.106,9.144 ; 230.988,8.992 230.835,9.144 213.106,9.144
  Bottom Layer w3.81: U5.11@154.5,-0.837 U5.5@154.5,4.663 154.5,7.993 155.194,8.687
  other v4: 32.715,9.195
I_O_IN1_UB1: U4_UB1.35 U55_UB1.69 | length 53
  Top Layer w0.254: U55_UB1.69@38.84,66.191 41.502,66.191 45.415,70.104 v1@47.854,70.104 ; v1(70.409,85.192) 70.561,85.344 74.574,85.344 77.112,87.882 U4_UB1.35@81.585,87.882
  Mid-Layer 2 w0.254: v1(47.854,70.079) 55.016,77.241 61.468,77.241 62.027,77.8 65.1,77.8 70.409,83.109 v1(70.409,85.192)
I_O_IN1_UB2: U4_UB2.35 U55_UB2.69 | length 42.6
  Top Layer w0.254: U4_UB2.35@179.629,93.474 178.458,93.474 178.257,93.675 177.038,93.675 175.92,92.558 175.92,86.716 178.46,84.176 183.286,84.176 185.191,82.271 v1(185.191,82.22) ; v1@193.726,66.496 U55_UB2.69@195.685,66.496
  Mid-Layer 2 w0.254: v1@185.217,82.22 185.217,77.165 190.525,71.857 190.525,70.51 193.04,67.996 193.04,67.031 v1(193.726,66.345)
I_O_IN2_UB1: U4_UB1.33 U55_UB1.72 | length 54.6
  Top Layer w0.254: U55_UB1.72@38.84,64.691 40.815,64.691 45.517,69.393 48.184,69.393 v1@48.717,69.926 ; v1(71.349,86.055) 74.041,86.055 76.867,88.882 79.382,88.882 U4_UB1.33@81.585,88.882
  Mid-Layer 2 w0.254: v1@48.692,69.926 55.372,76.606 61.697,76.606 62.255,77.165 65.608,77.165 71.374,82.931 v1@71.374,86.055
  other v1: 48.692,69.952
I_O_IN2_UB2: U4_UB2.33 U55_UB2.72 | length 42.3
  Top Layer w0.254: U4_UB2.33@179.629,92.474 177.234,92.474 176.479,91.719 176.479,87.046 178.714,84.811 183.744,84.811 v1(184.226,84.328) ; v1(193.116,65.546) 193.116,65.532 193.652,64.996 U55_UB2.72@195.685,64.996
  Mid-Layer 2 w0.254: v1@184.252,84.353 184.252,75.717 192.354,67.615 192.354,66.308 v1(193.116,65.546)
I_O_OUT1_UB1: U4_UB1.47 U55_UB1.73 | length 55.3
  Top Layer w0.254: U55_UB1.73@38.84,64.191 41.102,64.191 45.72,68.809 60.147,68.809 v1(60.274,68.936) ; v1@74.574,81.178 74.6,81.204 76.665,81.204 77.343,81.882 U4_UB1.47@81.585,81.882
  Mid-Layer 2 w0.254: v1@60.274,68.961 61.138,68.961 61.392,68.707 70.663,68.707 72.898,70.942 72.898,77.445 73.482,78.029 73.482,80.137 v1@74.549,81.204
  other v1: 74.574,81.191
I_O_OUT1_UB2: U4_UB2.47 U55_UB2.73 | length 44.9
  Top Layer w0.254: U4_UB2.47@179.629,99.474 v1(181.254,99.474) ; v1(192.456,65.1) 192.481,65.1 193.086,64.496 U55_UB2.73@195.685,64.496
  Mid-Layer 2 w0.254: v1(181.254,99.474) 181.178,99.398 181.178,98.552 180.315,97.688 180.315,89.764 183.439,86.639 183.439,75.616 190.221,68.834 190.221,67.335 v1(192.456,65.1)
I_O_OUT2_UB1: U4_UB1.46 U55_UB1.74 | length 55.6
  Top Layer w0.254: U55_UB1.74@38.84,63.691 41.42,63.691 45.928,68.199 v1@60.528,68.199 ; v1(76.302,81.89) 76.794,82.382 U4_UB1.46@81.585,82.382
  Mid-Layer 2 w0.254: v1@60.528,68.199 71.349,68.199 73.609,70.46 73.609,76.81 73.609,77.013 74.422,77.826 74.422,80.01 v1@76.298,81.886
  other v1: 60.655,68.199
I_O_OUT2_UB2: U4_UB2.46 U55_UB2.74 | length 46.9
  Top Layer w0.254: v1(177.749,99.162) 178.054,99.162 178.241,98.974 U4_UB2.46@179.629,98.974 ; v1(191.872,64.668) 192.544,63.996 U55_UB2.74@195.685,63.996
  Mid-Layer 2 w0.254: v1(177.749,99.162) 177.775,99.187 178.638,99.187 179.4,98.425 179.4,89.306 182.448,86.258 182.448,75.667 189.509,68.605 189.509,67.031 v1(191.872,64.668)
IGBT_FAULT1: R431.1 U68.44 | length 2.8
  Top Layer w0.381: R431.1@123.342,122.657 125.552,122.657 125.578,122.682 125.6,122.66 U68.44@125.6,122.12
IGBT_FAULT2: R435.1 U68.34 | length 3.2
  Top Layer w0.381: U68.34@133.6,122.12 133.654,122.174 R435.1@136.779,122.174
IGBT_FLT_UB1: R337_UB1.1 U4_UB1.44 U35_UB1.7 | length 67.4
  Top Layer w0.254: v2@43.967,105.74 42.977,104.75 42.977,96.52 44.78,94.717 48.87,94.717 51.054,92.532 v1(51.054,87.605) R337_UB1.1@51.054,86.258 ; v1(63.144,85.242) 65.354,83.033 v1(67.589,83.033) ; v1(69.164,82.728) 76.302,82.728 76.955,83.382 U4_UB1.44@81.585,83.382
  Mid-Layer 2 w0.254: v1(51.054,87.605) 52.324,87.605 53.238,86.69 53.238,85.801 53.873,85.166 54.775,85.166 55.054,85.446 62.941,85.446 v1(63.144,85.242) v1@63.221,85.319 ; v1(67.589,83.033) 67.894,82.728 v1(69.164,82.728)
  Bottom Layer w0.254: v2(44.044,105.74) 44.247,105.943 44.247,110.134 46.203,110.134 46.64,109.697 U35_UB1.7@46.64,108.636
IGBT_FLT_UB2: R337_UB2.1 U4_UB2.44 U35_UB2.7 | length 58.8
  Top Layer w0.254: U4_UB2.44@179.629,97.974 181.642,97.974 v1@181.813,98.146 ; R337_UB2.1@206.35,86.411 v1(206.35,89.256)
  Bottom Layer w0.254: v1(181.94,98.273) 182.575,98.273 185.509,95.339 205.384,95.339 ; v1(206.35,89.256) 205.384,90.221 205.384,95.339 ; 213.792,107.671 213.792,105.207 ; U35_UB2.7@213.792,109.093 213.792,105.207 ; 205.384,95.339 206.515,95.339 209.22,98.044 212.141,98.044 214.427,100.33 214.427,104.572 213.792,105.207
IGBT_FO_UB1: P4_UB1.7 U4_UB1.5 U68.14 | length 60.6
  Top Layer w0.254: U4_UB1.5@89.205,83.382 92.119,83.382 97.866,89.129 97.866,103.186 P4_UB1.7@100.533,105.853
  Top Layer w0.381: P4_UB1.7@100.533,105.853 104.731,105.853 108.479,109.601 121.234,109.601 123.495,107.34 126.187,107.34 127.2,108.353 U68.14@127.2,110.52
IGBT_FO_UB2: P4_UB2.7 U4_UB2.5 U68.31 | length 53.9
  Top Layer w0.254: P4_UB2.7@159.842,119.572 160.565,119.572 168.504,111.633 168.504,99.263 169.792,97.974 U4_UB2.5@172.72,97.974
  Top Layer w0.381: U68.31@135.4,118.72 157.175,118.72 158.013,119.558 159.828,119.558 P4_UB2.7@159.842,119.572
IGBT_PCTRLB_UB1: R258_UB1.1 U47_UB1.3 U55_UB1.28 | length 32.7
  Top Layer w0.254: v1(39.091,101.575) 39.091,99.339 44.577,93.853 47.854,93.853 48.641,93.066 48.641,82.245 49.04,81.846 U55_UB1.28@49.04,80.391
  Bottom Layer w0.254: U47_UB1.3@34.88,100.609 38.913,100.609 R258_UB1.1@39.091,100.432 ; R258_UB1.1@39.065,100.406 R258_UB1.1@39.091,100.432 ; v1(39.091,101.575) R258_UB1.1@39.091,100.432
IGBT_PCTRLB_UB2: R258_UB2.1 U47_UB2.3 U55_UB2.28 | length 31.3
  Top Layer w0.254: U55_UB2.28@205.885,80.696 205.885,82.695 207.315,84.125 207.315,85.18 207.302,85.193 207.302,85.571 207.315,85.584 v1(207.315,89.23) 207.315,90.551 R258_UB2.1@207.289,90.576
  Bottom Layer w0.254: v1(207.315,89.23) 207.315,89.637 206.121,90.83 206.121,93.853 207.493,95.225 211.455,95.225 216.256,100.025 216.256,101.422 216.891,102.057 U47_UB2.3@217.576,102.057
II_1_AC1_IN_UB1: C301_UB1.2 R19_UB1.1 R267_UB1.2 R298_UB1.2 | length 46.3
  Top Layer w0.254: R298_UB1.2@37.567,86.258 v1(37.567,87.782) ; C301_UB1.2@71.964,93.802 C301_UB1.2@72.014,93.751 ; v1(72.06,96.382) 72.04,96.362 R19_UB1.1@72.04,95.326 72.04,93.777 C301_UB1.2@72.014,93.751 ; R267_UB1.2@73.691,93.751 C301_UB1.2@72.014,93.751
  Mid-Layer 2 w0.254: v1(37.567,87.782) 44.907,87.782 47.244,90.119 47.244,91.872 ; 47.676,92.304 47.244,91.872 ; v1(72.06,96.382) 72.06,96.52 71.425,97.155 63.652,97.155 60.579,94.082 49.454,94.082 47.244,91.872
II_1_AC1_IN_UB2: C301_UB2.2 R19_UB2.1 R267_UB2.2 R298_UB2.2 | length 17.3
  Top Layer w0.254: R19_UB2.1@184.645,96.063 184.645,94.425 C301_UB2.2@184.658,94.412 R267_UB2.2@186.296,94.412 186.411,94.297 186.411,93.37 186.919,92.862 189.611,92.862 190.983,91.491 190.983,88.798 192.354,87.427 194.031,87.427 194.869,86.589 R298_UB2.2@194.869,86.487
II_1_AC1_UB1: P3_UB1.12 R272_UB1.1 | length 28.9
  Top Layer w0.254: v1(70.104,113.208) 69.469,112.573 69.469,103.911 70.561,102.819 R272_UB1.1@71.577,102.819
  Mid-Layer 2 w0.254: P3_UB1.12@65.329,128.047 65.329,127.457 69.19,123.596 69.19,114.122 v1(70.104,113.208)
II_1_AC1_UB2: P3_UB2.12 R272_UB2.1 | length 34
  Top Layer w0.254: v2(181.864,103.454) R272_UB2.1@183.007,103.454 R272_UB2.1@183.21,103.454
  Mid-Layer 2 w0.254: v2(181.864,103.454) 188.011,109.601 188.011,117.018 189.662,118.669 189.662,123.139 191.135,124.612 192.532,124.612 194.668,126.748 P3_UB2.12@194.668,129.952
II_1_AC2_IN_UB1: C325_UB1.2 R20_UB1.1 R286_UB1.2 R301_UB1.2 | length 50.3
  Top Layer w0.254: R301_UB1.2@38.989,86.258 v1(38.989,88.443) ; R286_UB1.2@75.469,93.751 75.52,93.701 C325_UB1.2@77.191,93.701 77.191,95.174 R20_UB1.1@77.216,95.199 77.216,96.19 v1(77.241,96.19)
  Mid-Layer 2 w0.254: v1(38.989,88.443) 39.014,88.468 44.196,88.468 46.38,90.653 46.38,92.405 48.819,94.844 60.249,94.844 63.271,97.866 75.565,97.866 v1(77.241,96.19)
II_1_AC2_IN_UB2: C325_UB2.2 R20_UB2.1 R286_UB2.2 R301_UB2.2 | length 15.2
  Top Layer w0.254: R286_UB2.2@187.896,94.361 189.56,94.361 189.572,94.349 R20_UB2.1@189.572,95.936 ; C325_UB2.2@189.586,94.336 191.795,92.126 191.795,89.433 193.218,88.011 195.377,88.011 196.297,87.091 R301_UB2.2@196.297,86.462
II_1_AC2_UB1: P3_UB1.27 R292_UB1.1 | length 36
  Top Layer w0.762: v1(78.054,102.768) 78.054,102.743 R292_UB1.1@79.223,102.743
  Mid-Layer 2 w0.254: P3_UB1.27@66.281,129.952 66.269,129.94 66.269,127.483 67.691,126.06 69.291,126.06 71.171,124.181 74.219,124.181 76.53,121.869 76.53,114.198 77.064,113.665 77.064,103.759 v1(78.054,102.768)
II_1_AC2_UB2: P3_UB2.27 R292_UB2.1 | length 32.1
  Top Layer w0.254: v2(191.541,103.734) 191.547,103.728 R292_UB2.1@191.547,102.641
  Mid-Layer 2 w0.254: v2(187.173,110.287) 186.944,110.287 187.223,110.007 187.223,117.678 188.824,119.278 188.824,123.749 190.373,125.298 191.973,125.298 193.716,127.041 P3_UB2.27@193.716,128.047
  Bottom Layer w0.254: v2(187.173,110.287) 186.944,110.287 191.541,105.689 v2(191.541,103.734)
II_1_AC3_IN_UB1: C299_UB1.2 R21_UB1.1 R265_UB1.2 R305_UB1.2 | length 47.2
  Top Layer w0.254: R305_UB1.2@40.386,86.258 v1(40.386,89.129) ; v1(72.06,103.886) C299_UB1.2@72.06,104.877 ; R21_UB1.1@72.06,106.451 C299_UB1.2@72.06,104.877 ; R265_UB1.2@73.665,104.877 C299_UB1.2@72.06,104.877
  Mid-Layer 2 w0.254: v1(40.386,89.129) 42.621,89.129 44.907,91.415 44.907,93.929 47.269,96.291 59.379,96.291 62.427,99.339 69.088,99.339 72.06,102.311 v1(72.06,103.886)
II_1_AC3_IN_UB2: C299_UB2.2 R21_UB2.1 R265_UB2.2 R305_UB2.2 | length 28.2
  Top Layer w0.254: R21_UB2.1@184.531,106.807 C299_UB2.2@184.531,105.258 184.556,105.232 R265_UB2.2@186.131,105.232 ; v1@195.758,88.722 197.714,86.766 R305_UB2.2@197.714,86.462
  Mid-Layer 2 w0.254: v1@185.369,105.232 185.369,101.936 186.233,101.072 186.233,96.205 193.462,88.976 193.421,88.976 193.65,88.748 v1(195.656,88.748)
  other v1: 185.369,105.207
II_1_AC3_UB1: P3_UB1.13 R270_UB1.1 | length 16.4
  Top Layer w0.254: P3_UB1.13@67.234,128.047 67.234,126.924 70.104,124.054 v1(70.104,123.825) ; v1(70.612,114.046) R270_UB1.1@71.628,114.046
  Mid-Layer 2 w0.254: v1@70.053,123.825 70.053,114.605 v1(70.612,114.046)
II_1_AC3_UB2: P3_UB2.13 R270_UB2.1 | length 23.4
  Top Layer w0.254: v2(182.042,114.198) 182.016,114.198 181.991,114.224 R270_UB2.1@183.159,114.224
  Mid-Layer 2 w0.254: v2(182.042,114.198) 186.157,118.313 186.157,123.927 188.849,126.619 192.227,126.619 192.763,127.155 P3_UB2.13@192.763,129.952
II_1_DC1_IN_UB1: C319_UB1.2 R22_UB1.1 R282_UB1.2 R304_UB1.2 | length 46.5
  Top Layer w0.254: R304_UB1.2@44.577,86.258 v1(44.577,89.916) ; v1(75.717,103.937) 75.692,103.962 R282_UB1.2@75.692,104.877 C319_UB1.2@77.267,104.877 R22_UB1.1@77.267,106.528
  Mid-Layer 2 w0.254: v1(44.577,89.916) 45.568,90.907 45.568,93.167 ; 45.872,93.472 45.568,93.167 ; v1(75.717,103.937) 71.603,99.822 70.663,99.822 69.469,98.628 62.89,98.628 59.842,95.58 47.981,95.58 45.568,93.167
II_1_DC1_IN_UB2: C319_UB2.2 R22_UB2.1 R282_UB2.2 R304_UB2.2 | length 31.9
  Top Layer w0.254: R282_UB2.2@187.782,105.283 187.808,105.258 C319_UB2.2@189.509,105.258 R22_UB2.1@189.509,106.832 ; v1(193.065,91.592) 198.272,91.592 201.981,87.884 R304_UB2.2@201.981,86.436
  Mid-Layer 2 w0.254: v1(188.646,105.232) 188.646,96.393 ; 189.484,95.555 188.646,96.393 ; v1(193.065,91.592) 193.065,91.643 188.646,96.063 188.646,96.393
II_1_DC1_UB1: P3_UB1.28 R288_UB1.1 | length 24.3
  Top Layer w0.254: v1(77.978,114.097) R288_UB1.1@79.172,114.097
  Mid-Layer 2 w0.254: P3_UB1.28@68.186,129.952 68.186,127.394 69.037,126.543 69.774,126.543 71.222,125.095 75.971,125.095 77.343,123.723 77.343,114.732 v1(77.978,114.097)
II_1_DC1_UB2: P3_UB2.28 R288_UB2.1 | length 16
  Top Layer w0.254: R288_UB2.1@191.491,113.69 v2(191.491,114.579) ; P3_UB2.28@191.811,128.047 191.811,126.314 192.608,125.517 v2@192.608,122.987
  Mid-Layer 2 w0.254: v2(191.491,114.579) 191.491,116.053 190.5,117.043 190.5,120.853 v2@192.659,123.012
  other v2: 192.684,122.987
IO_IN1_UB1: P4_UB1.14 P4_UB2.5 U4_UB1.14 U4_UB2.2 | length 133
  Top Layer w0.254: U4_UB1.14@89.205,87.882 91.895,87.882 94.412,90.399 94.412,114.656 99.609,119.853 P4_UB1.14@100.533,119.853 ; P4_UB2.5@159.842,123.572 160.73,123.572 169.875,114.427 169.875,99.771 170.172,99.474 U4_UB2.2@172.72,99.474
  Top Layer w0.381: P4_UB1.14@100.533,119.853 101.127,119.853 103.454,117.526 v2(114.402,117.526)
  Mid-Layer 2 w0.381: v2@114.402,117.5 116.434,117.5 117.094,118.161 153.441,118.161 158.853,123.572 P4_UB2.5@159.842,123.572
IO_IN1_UB2: P4_UB1.5 P4_UB2.14 U4_UB1.2 U4_UB2.14 | length 106.8
  Top Layer w0.254: U4_UB1.2@89.205,81.882 92.561,81.882 98.984,88.305 98.984,100.304 P4_UB1.5@100.533,101.853 ; P4_UB2.14@159.842,105.572 160.468,105.572 164.287,101.752 164.287,98.073 168.886,93.474 U4_UB2.14@172.009,93.474
  Mid-Layer 2 w0.381: P4_UB1.5@100.533,101.853 102.767,101.853 103.784,102.87 138.608,102.87 140.335,104.597 158.293,104.597 159.106,105.41 159.68,105.41 P4_UB2.14@159.842,105.572
IO_IN2_UB1: P4_UB1.15 P4_UB2.6 U4_UB1.16 U4_UB2.3 | length 131.7
  Top Layer w0.254: U4_UB1.16@89.205,88.882 91.955,88.882 93.853,90.78 93.853,115.173 P4_UB1.15@100.533,121.853 ; P4_UB2.6@159.842,121.572 160.343,121.572 169.139,112.776 169.139,99.517 169.681,98.974 U4_UB2.3@172.72,98.974
  Top Layer w0.381: P4_UB1.15@100.533,121.853 102.404,121.853 105.41,118.847 110.261,118.847 110.719,118.389 115.24,118.389 v2(115.24,118.491) ; v2(153.543,119.736) 156.667,119.736 158.504,121.572 ; 158.877,121.572 158.504,121.572 ; P4_UB2.6@159.842,121.572 158.504,121.572
  Mid-Layer 2 w0.381: v2@115.303,118.427 115.849,118.974 152.781,118.974 v2(153.543,119.736)
IO_IN2_UB2: P4_UB1.6 P4_UB2.15 U4_UB1.3 U4_UB2.16 | length 108.2
  Top Layer w0.254: U4_UB1.3@89.205,82.382 92.059,82.382 98.501,88.824 98.501,101.821 P4_UB1.6@100.533,103.853 ; P4_UB2.15@159.842,103.572 160.563,103.572 163.652,100.482 163.652,97.841 169.019,92.474 U4_UB2.16@172.009,92.474
  Top Layer w0.381: v2(157.683,105.715) 157.48,105.715 157.683,105.512 157.683,105.156 159.267,103.572 P4_UB2.15@159.842,103.572
  Mid-Layer 2 w0.381: P4_UB1.6@100.533,103.853 100.678,103.708 138.151,103.708 140.614,106.172 157.023,106.172 157.48,105.715 v2(157.683,105.715)
ISO_+15V_UB1: C12_UB1.1 C13_UB1.2 C14_UB1.2 C15_UB1.2 C256_UB1.1 C257_UB1.1 C278_UB1.1 C279_UB1.1 C280_UB1.2 C281_UB1.2 C282_UB1.2 C283_UB1.1 C305_UB1.2 C306_UB1.2 C307_UB1.2 C308_UB1.2 LED10_UB1.1 P1_UB1.1 P3_UB1.1 P3_UB1.16 R192_UB1.1 U3_UB1.6 U35_UB1.1 U35_UB1.4 U37_UB1.6 U38_UB1.6 U40_UB1.6 U41_UB1.6 U43_UB1.6 U44_UB1.6 U45_UB1.6 UP6_UB1.3 | length 120.6
  Top Layer w0.762: C283_UB1.1@27.407,123.825 LED10_UB1.1@27.407,126.39 ; C283_UB1.1@28.118,123.622 28.143,123.647 28.321,123.825 ; 41.377,124.892 41.385,124.892 41.808,124.892 44.094,124.892 ; 41.385,122.851 43.045,124.511 C15_UB1.2@44.145,124.511 44.145,125.298 ; 41.385,124.469 41.427,124.511 ; 43.18,126.263 44.145,125.298 ; 43.663,126.746 44.145,126.263 44.145,125.298 ; v2(44.069,114.732) 44.069,116.281 44.577,116.789 45.644,116.789 U44_UB1.6@45.904,117.05 ; C281_UB1.2@45.745,120.548 45.745,117.209 U44_UB1.6@45.904,117.05 ; U44_UB1.6@45.904,117.653 U44_UB1.6@45.904,117.05 ; C14_UB1.2@49.682,120.625 C282_UB1.2@51.257,120.625 U37_UB1.6@51.257,118.237 ; v2(49.708,118.08) 51.1,118.08 U37_UB1.6@51.257,118.237 ; U37_UB1.6@51.257,117.196 U37_UB1.6@51.257,118.237 ; C256_UB1.1@55.347,120.929 55.428,120.848 C256_UB1.1@55.428,120.218 55.753,120.218 57.282,118.689 U40_UB1.6@57.282,117.653 ; C257_UB1.1@61.341,120.218 62.763,120.218 62.896,120.086 U43_UB1.6@62.896,117.5
  Top Layer w2.54: P1_UB1.1@21.793,125.578 24.257,125.578 ; C283_UB1.1@28.118,123.622 C279_UB1.1@34.31,123.622 C278_UB1.1@38.044,123.622 40.615,123.622 41.385,122.851 ; C12_UB1.1@30.652,123.647 28.143,123.647 C283_UB1.1@26.893,123.647 ; 41.427,124.511 41.808,124.892 43.18,126.263 ; 43.22,127.548 41.935,126.263 ; v2(44.069,114.732) 44.028,114.691 UP6_UB1.3@41.385,114.691 41.385,122.851 ; 44.729,130.124 43.663,129.057 ; 24.257,125.578 26.492,125.578 26.518,125.603 26.518,124.023 C283_UB1.1@26.893,123.647 ; 24.257,125.578 26.187,123.647 C283_UB1.1@26.893,123.647 ; 41.385,122.851 41.385,124.469 41.385,124.892 41.385,125.713 ; 41.385,125.713 41.385,126.78 43.663,129.057 ; 41.385,125.713 41.935,126.263 ; 41.935,126.263 43.18,126.263 ; 43.18,126.263 43.663,126.746 43.663,129.057
  Bottom Layer w0.508: U38_UB1.6@65.43,117.5 v2(65.43,119.71)
  Bottom Layer w0.762: v2(44.069,114.732) 45.237,114.732 45.237,116.713 R192_UB1.1@45.212,116.738 ; v2(45.72,119.456) 45.745,119.482 C305_UB1.2@45.745,120.548 C306_UB1.2@47.168,120.548 ; U35_UB1.4@49.18,114.783 49.18,115.626 49.708,116.154 v2(49.708,118.08) 49.708,118.186 49.352,118.542 49.352,120.32 C308_UB1.2@49.682,120.65 C307_UB1.2@51.257,120.65 ; U41_UB1.6@53.98,117.653 53.98,120.325 54.61,120.955 v2(54.991,120.955) v2(56.058,120.955) ; U45_UB1.6@59.822,117.653 59.822,118.928 60.833,119.939 v2(60.833,120.853)
  Bottom Layer w2.54: 39.319,116.611 41.123,116.611 41.385,116.349 UP6_UB1.3@41.385,114.691
  other v2: 62.001,120.828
